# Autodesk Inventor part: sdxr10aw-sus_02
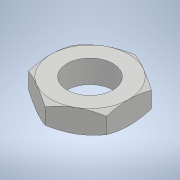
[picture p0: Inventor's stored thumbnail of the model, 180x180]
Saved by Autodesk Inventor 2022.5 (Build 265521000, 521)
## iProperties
Part Number: sdxr10aw-sus_02
Material: 一般
Document SubType Name: Modeling
Designer: ImaoCorp
Density: 1 g/cm^3
Appearance: 既定
Author: ImaoCorp
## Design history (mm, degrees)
feature "sdxr10aw-sus_02"
node "ソリッド1"
